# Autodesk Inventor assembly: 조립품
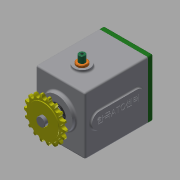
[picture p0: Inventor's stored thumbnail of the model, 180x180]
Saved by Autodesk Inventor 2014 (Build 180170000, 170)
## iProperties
Created: 2018-12
Part Number: 조립품
Document SubType Name: Assembly
Designer: kh
Author: kh
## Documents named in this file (16)
- C:\Users\kh\Desktop\381207V1017\조립품.iam
- C:\Users\kh\Desktop\381207V1017\본체.ipt
- C:\Users\kh\Desktop\381207V1017\가변스프링.ipt
- C:\Users\kh\Desktop\381207V1017\멈춤나사 M3x8.ipt
- C:\Users\kh\Desktop\381207V1017\메인 기어 축.ipt
- C:\Users\kh\Desktop\381207V1017\베어링 608.ipt
- C:\Users\kh\Desktop\381207V1017\베어링 6003.ipt
- C:\Users\kh\Desktop\381207V1017\볼트 M4 x 10.ipt
- C:\Users\kh\Desktop\381207V1017\부시.ipt
- C:\Users\kh\Desktop\381207V1017\서브 기어 축.ipt
- C:\Users\kh\Desktop\381207V1017\스프로킷.ipt
- C:\Users\kh\Desktop\381207V1017\슬라이더.ipt
- C:\Users\kh\Desktop\381207V1017\오일 실 8 22 7.ipt
- C:\Users\kh\Desktop\381207V1017\오일 실 17 32 8.ipt
- C:\Users\kh\Desktop\381207V1017\커버.ipt
- C:\Users\kh\Desktop\381207V1017\키 5 x 5 x 18.ipt
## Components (1 placed, 1 different names)
1. 가변스프링:1
